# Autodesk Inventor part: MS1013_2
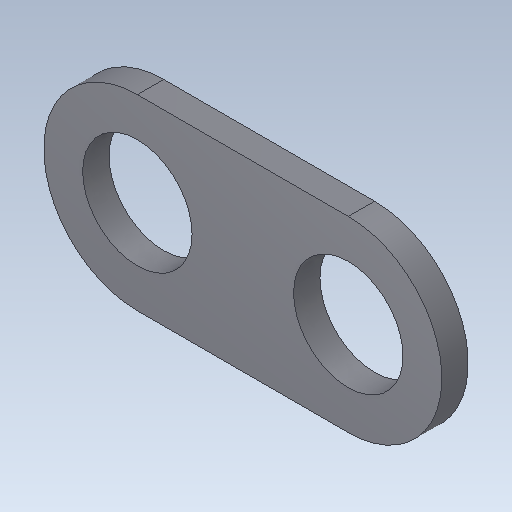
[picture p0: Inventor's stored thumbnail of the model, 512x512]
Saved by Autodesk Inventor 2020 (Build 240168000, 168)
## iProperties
Created: 2015-11
Part Number: MS1013_2
Material: Ogólny
Document SubType Name: Modeling
Designer: Tomasz
Density: 1 g/cm^3
Appearance: Domyślna
Sending System: SolidWorks 2017
Last Author: Tomasz
Last Saved: 2017-09-17
Author: Tomasz
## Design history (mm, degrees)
feature "Imported1"
node "Bryła1"
